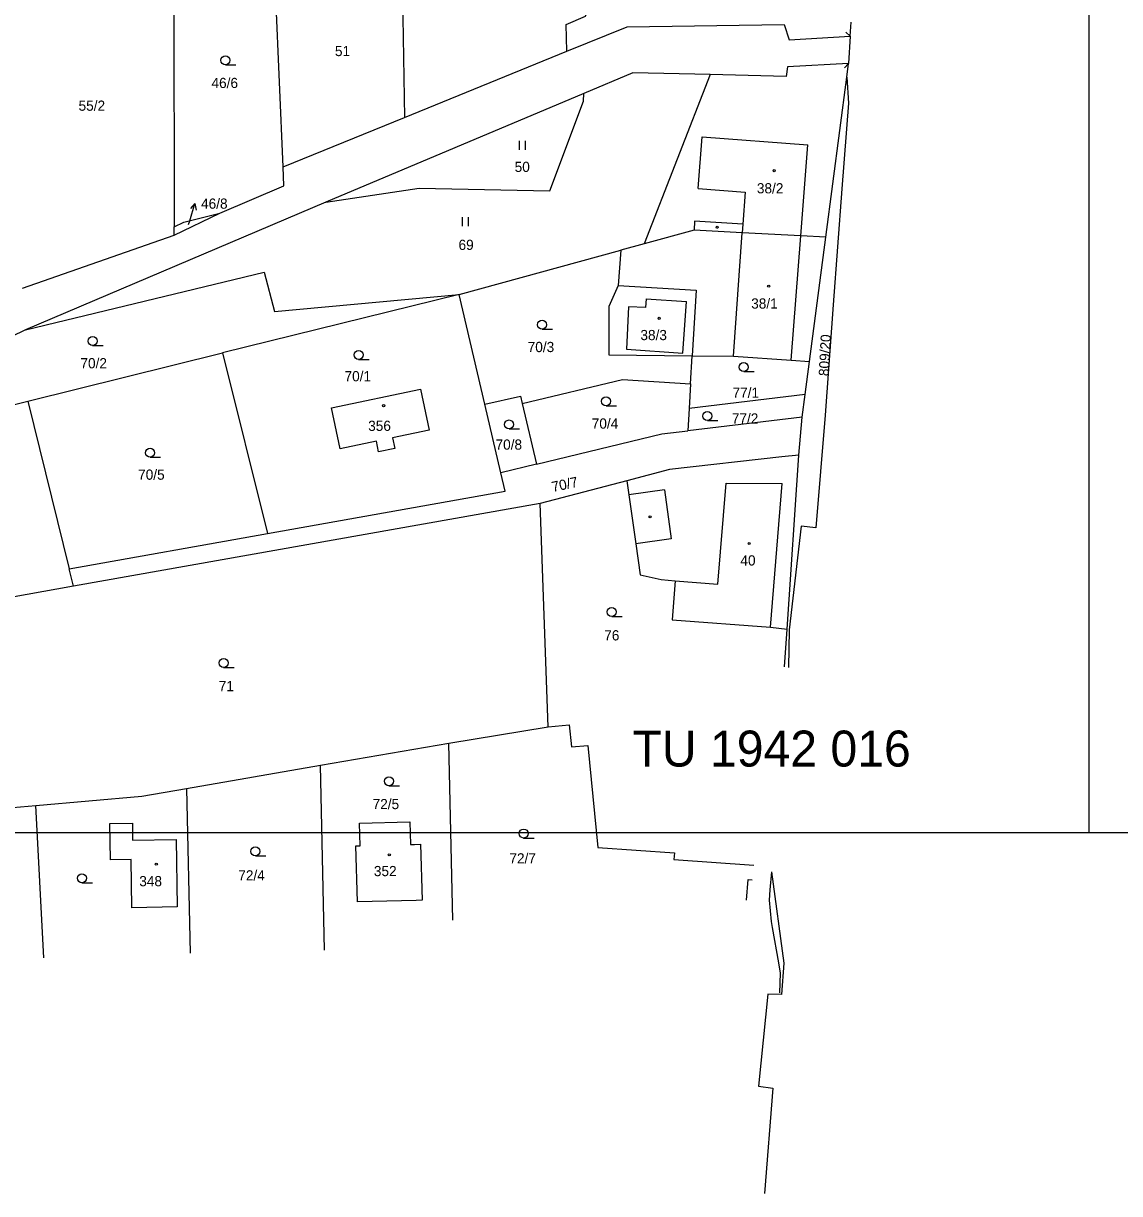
# Model space of a CAD drawing. Extents: x -553916 to -552953, y -1067470 to -1066637.
# Drawn here: x -553477.6 to -553294.9, y -1067470.4 to -1067275.4 of the extents above; entities that cross this region are included whole.
import ezdxf

# ---------------------------------------------------------------- set-up
doc = ezdxf.new("R2010")
doc.units = 0
for name, color, linetype in [('Hranice parcel', 7, 'Continuous'), ('Parcelní čísla', 7, 'Continuous'), ('Pop  PČ popisy', 7, 'Continuous'), ('Vnitřní kresba', 7, 'Continuous'), ('Vrstva 1', 7, 'Continuous'), ('Vrstva 2', 7, 'Continuous'), ('Značky budov', 7, 'Continuous'), ('Značky kultur', 7, 'Continuous')]:
    doc.layers.add(name, color=color, linetype=linetype)

msp = doc.modelspace()

# ---------------------------------------------------------------- linework, layer by layer
at = {"layer": 'Hranice parcel'}
for p, q in [((-553452.56, -1067263.4), (-553452.48, -1067309.26)), ((-553434.32, -1067299.29), (-553435.83, -1067263.59)), ((-553414.54, -1067263.83), (-553414.1, -1067291.02)), ((-553339.78, -1067277.49), (-553339.64, -1067275.16)), ((-553339.78, -1067277.49), (-553340.06, -1067282.03)), ((-553414.1, -1067291.02), (-553387.06, -1067279.96)), ((-553340.36, -1067284.3), (-553340.06, -1067282.03)), ((-553363.12, -1067283.9), (-553374.13, -1067312.09)), ((-553343.86, -1067311), (-553340.36, -1067284.3)), ((-553340.36, -1067284.3), (-553340.08, -1067288.63)), ((-553384.22, -1067287.06), (-553427.2, -1067305.17)), ((-553434.32, -1067299.29), (-553414.1, -1067291.02)), ((-553427.2, -1067305.17), (-553477.28, -1067326.46)), ((-553452.48, -1067310.66), (-553444.86, -1067306.97)), ((-553452.48, -1067310.66), (-553452.48, -1067309.26)), ((-553477.8, -1067319.49), (-553452.48, -1067310.66)), ((-553346.58, -1067331.73), (-553343.86, -1067311)), ((-553404.99, -1067320.53), (-553378.02, -1067313.15)), ((-553378.02, -1067313.15), (-553378.48, -1067319.05)), ((-553374.13, -1067312.09), (-553378.02, -1067313.15)), ((-553378.48, -1067319.05), (-553365.46, -1067319.83)), ((-553404.99, -1067320.53), (-553444.42, -1067330.3)), ((-553400.73, -1067338.86), (-553404.99, -1067320.53)), ((-553365.46, -1067319.83), (-553366.12, -1067330.75)), ((-553477.28, -1067326.46), (-553508.22, -1067341.4)), ((-553476.87, -1067338.35), (-553444.42, -1067330.3)), ((-553444.42, -1067330.3), (-553436.96, -1067360.4)), ((-553366.4, -1067335.42), (-553366.12, -1067330.75)), ((-553347.3, -1067337.24), (-553346.58, -1067331.73)), ((-553394.49, -1067338.71), (-553377.76, -1067334.7)), ((-553377.76, -1067334.7), (-553366.4, -1067335.42)), ((-553366.4, -1067335.42), (-553366.65, -1067339.54)), ((-553347.3, -1067337.24), (-553366.65, -1067339.54)), ((-553347.79, -1067341.01), (-553347.3, -1067337.24)), ((-553504.63, -1067345.23), (-553476.87, -1067338.35)), ((-553476.87, -1067338.35), (-553470.01, -1067366.29)), ((-553398.02, -1067350.28), (-553400.73, -1067338.86)), ((-553394.49, -1067338.71), (-553392.07, -1067348.84)), ((-553366.65, -1067339.54), (-553366.88, -1067343.28)), ((-553347.79, -1067341.01), (-553366.88, -1067343.28)), ((-553348.37, -1067347.33), (-553347.79, -1067341.01)), ((-553392.07, -1067348.84), (-553398.02, -1067350.28)), ((-553350.29, -1067376.34), (-553348.37, -1067347.33)), ((-553397.3, -1067353.33), (-553398.02, -1067350.28)), ((-553377.01, -1067351.59), (-553391.49, -1067355.38)), ((-553436.96, -1067360.4), (-553397.3, -1067353.33)), ((-553391.49, -1067355.38), (-553469.3, -1067369.18)), ((-553390.16, -1067392.62), (-553391.49, -1067355.38)), ((-553470.01, -1067366.29), (-553436.96, -1067360.4)), ((-553469.3, -1067369.18), (-553470.01, -1067366.29)), ((-553469.3, -1067369.18), (-553505.45, -1067375.59)), ((-553350.77, -1067382.61), (-553350.29, -1067376.34)), ((-553349.97, -1067376.47), (-553350.08, -1067382.76)), ((-553406.69, -1067395.35), (-553390.16, -1067392.62)), ((-553390.16, -1067392.62), (-553386.64, -1067392.27)), ((-553428.1, -1067399.03), (-553406.69, -1067395.35)), ((-553406.03, -1067424.86), (-553406.69, -1067395.35)), ((-553450.42, -1067402.9), (-553428.1, -1067399.03)), ((-553427.43, -1067429.84), (-553428.1, -1067399.03)), ((-553450.42, -1067402.9), (-553449.81, -1067430.36)), ((-553504.51, -1067408.36), (-553475.58, -1067405.74)), ((-553474.2, -1067431.11), (-553475.58, -1067405.74))]:
    msp.add_line(p, q, dxfattribs=at)
for points in [[(-553387.06, -1067279.96), (-553387.14, -1067275.52), (-553383.92, -1067274.15), (-553380.89, -1067266)], [(-553387.06, -1067279.96), (-553376.95, -1067275.94), (-553350.82, -1067275.55), (-553349.97, -1067278.1), (-553339.78, -1067277.49)], [(-553340.06, -1067282.03), (-553350.24, -1067282.62), (-553350.46, -1067284.19), (-553363.12, -1067283.9)], [(-553363.12, -1067283.9), (-553376.01, -1067283.6), (-553384.22, -1067287.06)], [(-553427.2, -1067305.17), (-553411.63, -1067302.82), (-553389.87, -1067303.29), (-553384.27, -1067288.32), (-553384.22, -1067287.06)], [(-553340.08, -1067288.63), (-553341.21, -1067302.95), (-553342.64, -1067322.28), (-553343.99, -1067340.66), (-553345.54, -1067359.46), (-553347.99, -1067359.17), (-553349.97, -1067376.47)], [(-553444.86, -1067306.97), (-553434.22, -1067302.44), (-553434.32, -1067299.29)], [(-553452.48, -1067309.26), (-553450.87, -1067308.5), (-553444.86, -1067306.97)], [(-553343.86, -1067311), (-553348.02, -1067310.79), (-553357.81, -1067310.29), (-553365.83, -1067309.82), (-553374.13, -1067312.09)], [(-553477.28, -1067326.46), (-553437.51, -1067316.85), (-553435.74, -1067323.39), (-553404.99, -1067320.53)], [(-553378.48, -1067319.05), (-553380.03, -1067322.56), (-553380.01, -1067330.61), (-553366.12, -1067330.75)], [(-553366.12, -1067330.75), (-553359.25, -1067330.82), (-553349.63, -1067331.51), (-553346.58, -1067331.73)], [(-553426.29, -1067339.42), (-553411.41, -1067336.33), (-553409.99, -1067343.16), (-553416.11, -1067344.46), (-553415.72, -1067346.24), (-553418.41, -1067346.79), (-553418.75, -1067345.01), (-553424.84, -1067346.28), (-553426.29, -1067339.42)], [(-553400.73, -1067338.86), (-553394.78, -1067337.5), (-553394.49, -1067338.71)], [(-553392.07, -1067348.84), (-553371.19, -1067343.77), (-553366.88, -1067343.28)], [(-553348.37, -1067347.33), (-553351.19, -1067347.59), (-553369.94, -1067349.74), (-553377.01, -1067351.59)], [(-553377.01, -1067351.59), (-553376.68, -1067353.95), (-553375.53, -1067362.12), (-553374.8, -1067367.29), (-553371.29, -1067368.08), (-553368.95, -1067368.27), (-553369.45, -1067374.77), (-553353.09, -1067376.03), (-553350.29, -1067376.34)], [(-553386.64, -1067392.27), (-553386.27, -1067395.98), (-553383.55, -1067395.71), (-553381.86, -1067412.72), (-553369.09, -1067413.61), (-553369.18, -1067414.74), (-553355.88, -1067415.67)], [(-553475.58, -1067405.74), (-553457.9, -1067404.18), (-553450.42, -1067402.9)], [(-553451.98, -1067422.65), (-553459.53, -1067422.78), (-553459.64, -1067414.75), (-553463.13, -1067414.82), (-553463.23, -1067408.76), (-553459.46, -1067408.68), (-553459.43, -1067411.53), (-553452.14, -1067411.41), (-553451.98, -1067422.65)], [(-553421.58, -1067408.69), (-553413.18, -1067408.46), (-553413.1, -1067412.24), (-553412.4, -1067412.22), (-553411.4, -1067412.21), (-553411.17, -1067421.52), (-553412.17, -1067421.55), (-553421.95, -1067421.8), (-553422.19, -1067412.47), (-553421.49, -1067412.45), (-553421.58, -1067408.69)], [(-553352.92, -1067416.78), (-553350.84, -1067432), (-553351.25, -1067437.24), (-553353.52, -1067437.17), (-553355.07, -1067452.55), (-553352.7, -1067452.85), (-553354.07, -1067470.44)], [(-553352.92, -1067416.78), (-553353.2, -1067419.82), (-553353.31, -1067421.52), (-553352.96, -1067425.1), (-553352.82, -1067426.1), (-553351.75, -1067431.96), (-553351.47, -1067433.71), (-553351.58, -1067436.96)], [(-553357.09, -1067421.54), (-553356.81, -1067418.1), (-553356.11, -1067418.14)]]:
    msp.add_lwpolyline(points, dxfattribs=at)
at = {"layer": 'Pop  PČ popisy'}
for p, q in [((-553449.9, -1067308.26), (-553449.02, -1067305.39)), ((-553449.02, -1067305.39), (-553449.79, -1067306.2)), ((-553449.02, -1067305.39), (-553448.84, -1067306.49)), ((-553450.09, -1067308.86), (-553449.9, -1067308.26))]:
    msp.add_line(p, q, dxfattribs=at)
at = {"layer": 'Vnitřní kresba'}
for p, q in [((-553340.54, -1067276.83), (-553339.78, -1067277.49)), ((-553340.77, -1067282.74), (-553340.06, -1067282.03)), ((-553365.12, -1067302.9), (-553364.45, -1067294.25)), ((-553364.45, -1067294.25), (-553346.84, -1067295.62)), ((-553348.02, -1067310.79), (-553346.84, -1067295.62)), ((-553365.12, -1067302.9), (-553357.33, -1067303.51)), ((-553357.33, -1067303.51), (-553357.71, -1067308.81)), ((-553365.74, -1067308.34), (-553365.83, -1067309.82)), ((-553357.71, -1067308.81), (-553365.74, -1067308.34)), ((-553357.71, -1067308.81), (-553357.81, -1067310.29)), ((-553359.25, -1067330.82), (-553357.81, -1067310.29)), ((-553349.63, -1067331.51), (-553348.02, -1067310.79)), ((-553373.83, -1067321.26), (-553373.9, -1067322.72)), ((-553373.83, -1067321.26), (-553367.11, -1067321.73)), ((-553367.71, -1067330.32), (-553367.11, -1067321.73)), ((-553376.74, -1067322.59), (-553377.06, -1067329.65)), ((-553373.9, -1067322.72), (-553376.74, -1067322.59)), ((-553377.06, -1067329.65), (-553367.71, -1067330.32)), ((-553361.86, -1067368.85), (-553360.49, -1067351.99)), ((-553360.49, -1067351.99), (-553351.11, -1067352.07)), ((-553353.09, -1067376.03), (-553351.11, -1067352.07)), ((-553370.77, -1067353.12), (-553376.68, -1067353.95)), ((-553370.77, -1067353.12), (-553369.62, -1067361.3)), ((-553369.62, -1067361.3), (-553375.53, -1067362.12)), ((-553368.95, -1067368.27), (-553361.86, -1067368.85))]:
    msp.add_line(p, q, dxfattribs=at)
at = {"layer": 'Vrstva 1'}
msp.add_line((-552953.11, -1067410.27), (-553794.11, -1067410.27), dxfattribs=at)
msp.add_lwpolyline([(-553800, -1067410.27), (-553800, -1067100), (-553300, -1067100), (-553300, -1067410.27)], dxfattribs=at)
at = {"layer": 'Značky budov'}
for centre in [(-553352.47, -1067299.9), (-553361.96, -1067309.34), (-553353.38, -1067319.15), (-553371.64, -1067324.53), (-553417.57, -1067339.08), (-553373.16, -1067357.63), (-553356.64, -1067362.06), (-553455.47, -1067415.53), (-553416.63, -1067413.97)]:
    msp.add_circle(centre, 0.175, dxfattribs=at)
at = {"layer": 'Značky kultur'}
for p, q in [((-553443.94, -1067282.25), (-553442.19, -1067282.25)), ((-553394.95, -1067296.43), (-553394.95, -1067294.93)), ((-553393.95, -1067296.43), (-553393.95, -1067294.93)), ((-553404.41, -1067309.15), (-553404.41, -1067307.65)), ((-553403.41, -1067309.15), (-553403.41, -1067307.65)), ((-553391.15, -1067326.33), (-553389.4, -1067326.33)), ((-553466.08, -1067329.06), (-553464.33, -1067329.06)), ((-553421.74, -1067331.37), (-553419.99, -1067331.37)), ((-553357.54, -1067333.41), (-553355.79, -1067333.41)), ((-553380.49, -1067339.11), (-553378.74, -1067339.11)), ((-553396.66, -1067342.97), (-553394.91, -1067342.97)), ((-553363.6, -1067341.56), (-553361.85, -1067341.56)), ((-553456.5, -1067347.69), (-553454.75, -1067347.69)), ((-553379.55, -1067374.22), (-553377.8, -1067374.22)), ((-553444.25, -1067382.73), (-553442.5, -1067382.73)), ((-553416.68, -1067402.44), (-553414.93, -1067402.44)), ((-553394.23, -1067411.16), (-553392.48, -1067411.16)), ((-553438.96, -1067414.14), (-553437.21, -1067414.14)), ((-553467.88, -1067418.61), (-553466.13, -1067418.61))]:
    msp.add_line(p, q, dxfattribs=at)
for centre in [(-553443.94, -1067281.5), (-553391.15, -1067325.58), (-553466.08, -1067328.31), (-553421.74, -1067330.62), (-553357.54, -1067332.66), (-553380.49, -1067338.36), (-553363.6, -1067340.81), (-553396.66, -1067342.22), (-553456.5, -1067346.94), (-553379.55, -1067373.47), (-553444.25, -1067381.98), (-553416.68, -1067401.69), (-553394.23, -1067410.41), (-553438.96, -1067413.39), (-553467.88, -1067417.86)]:
    msp.add_circle(centre, 0.75, dxfattribs=at)

# ---------------------------------------------------------------- texts
at = {"layer": 'Parcelní čísla'}
for s, p in [('51', (-553425.69, -1067280.81)), ('46/6', (-553446.27, -1067286.13)), ('55/2', (-553468.43, -1067289.92)), ('50', (-553395.73, -1067300.12)), ('38/2', (-553355.35, -1067303.69)), ('46/8', (-553448.01, -1067306.25)), ('69', (-553405.09, -1067313.12)), ('38/1', (-553356.3, -1067322.9)), ('38/3', (-553374.77, -1067328.16)), ('70/3', (-553393.56, -1067330.15)), ('70/2', (-553468.12, -1067332.86)), ('70/1', (-553424.09, -1067335.02)), ('77/1', (-553359.41, -1067337.77)), ('70/4', (-553382.88, -1067342.91)), ('77/2', (-553359.53, -1067342.07)), ('356', (-553420.15, -1067343.29)), ('70/8', (-553398.92, -1067346.42)), ('70/5', (-553458.5, -1067351.43)), ('40', (-553358.1, -1067365.73)), ('76', (-553380.8, -1067378.22)), ('71', (-553445.06, -1067386.68)), ('72/5', (-553419.41, -1067406.35)), ('72/7', (-553396.61, -1067415.4)), ('72/4', (-553441.81, -1067418.24)), ('352', (-553419.2, -1067417.52)), ('348', (-553458.31, -1067419.2))]:
    msp.add_text(s, height=1.7, dxfattribs=at).set_placement(p)
for s, rotation, p in [('809/20', 87, (-553343.36, -1067334.19)), ('70/7', 12, (-553389.37, -1067353.49))]:
    msp.add_text(s, height=1.7, rotation=rotation, dxfattribs=at).set_placement(p)
at = {"layer": 'Vrstva 2'}
msp.add_text('TU 1942 016', height=6, dxfattribs=at).set_placement((-553376.09, -1067399.25))

doc.saveas('drawing.dxf')
